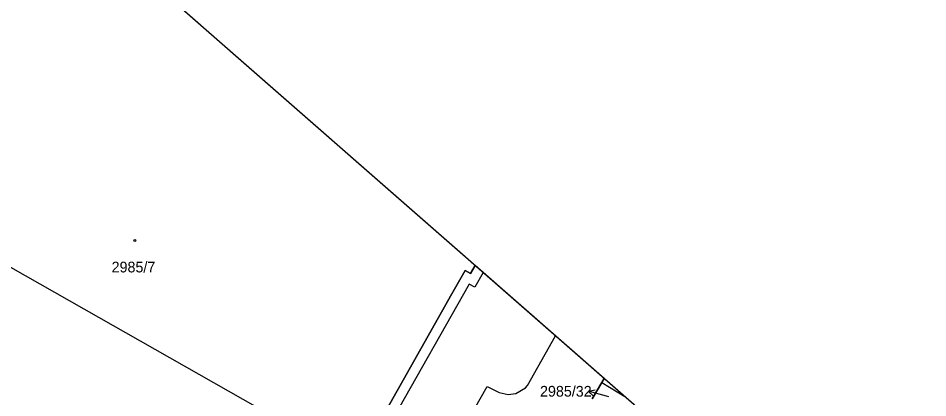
# Model space of a CAD drawing. Extents: x -620475 to -619963, y -1123010 to -1122510.
# Drawn here: x -620107.7 to -619962.9, y -1122744.6 to -1122684.3 of the extents above; entities that cross this region are included whole.
import ezdxf

# ---------------------------------------------------------------- set-up
doc = ezdxf.new("R2010")
doc.units = 0
for name, color, linetype in [('Hranice parcel', 7, 'Continuous'), ('Parcelní čísla', 7, 'Continuous'), ('Pop  PČ popisy', 7, 'Continuous'), ('Rámečky', 7, 'Continuous'), ('Rámečky-tisk', 7, 'Continuous'), ('Vnitřní kresba', 7, 'Continuous'), ('Věcná břemena k části', 7, 'Continuous'), ('Značky budov', 7, 'Continuous')]:
    doc.layers.add(name, color=color, linetype=linetype)

msp = doc.modelspace()

# ---------------------------------------------------------------- linework, layer by layer
at = {"layer": 'Hranice parcel'}
for p, q in [((-620014.43, -1122741.56), (-620014.82, -1122742.21)), ((-620014.82, -1122742.21), (-620016.36, -1122744.78)), ((-620014.82, -1122742.21), (-620011.18, -1122744.41))]:
    msp.add_line(p, q, dxfattribs=at)
for points in [[(-620129.52, -1122710.96), (-620124.48, -1122713.98), (-620124.94, -1122714.79), (-620058.31, -1122752.59), (-620054.51, -1122754.74), (-620054.56, -1122754.84)], [(-620054.56, -1122754.84), (-620053.98, -1122755.17), (-620038.67, -1122728.11), (-620036.56, -1122724.38), (-620035.71, -1122724.86), (-620034.98, -1122723.59)]]:
    msp.add_lwpolyline(points, dxfattribs=at)
at = {"layer": 'Pop  PČ popisy'}
for p, q in [((-620016.98, -1122743.6), (-620015.88, -1122743.38)), ((-620014.08, -1122744.38), (-620016.98, -1122743.6)), ((-620016.98, -1122743.6), (-620016.14, -1122744.35)), ((-620013.72, -1122744.48), (-620014.08, -1122744.38))]:
    msp.add_line(p, q, dxfattribs=at)
at = {"layer": 'Rámečky'}
msp.add_line((-619962.95, -1122786.6), (-620279.07, -1122510.07), dxfattribs=at)
at = {"layer": 'Rámečky-tisk'}
msp.add_lwpolyline([(-620158.49, -1123010.14), (-619962.95, -1122786.6), (-620279.07, -1122510.07)], dxfattribs=at)
at = {"layer": 'Vnitřní kresba'}
for p, q in [((-620033.71, -1122724.7), (-620035.03, -1122727.06)), ((-620035.9, -1122726.57), (-620054.1, -1122758.47)), ((-620035.03, -1122727.06), (-620035.9, -1122726.57)), ((-620026.67, -1122742.66), (-620022.17, -1122734.8)), ((-620041.55, -1122757.64), (-620033.04, -1122742.83)), ((-620033.04, -1122742.83), (-620031.15, -1122743.81)), ((-620028.49, -1122743.97), (-620026.97, -1122743.05)), ((-620026.97, -1122743.05), (-620026.67, -1122742.66)), ((-620031.15, -1122743.81), (-620029.7, -1122744.11)), ((-620029.7, -1122744.11), (-620028.49, -1122743.97))]:
    msp.add_line(p, q, dxfattribs=at)
at = {"layer": 'Věcná břemena k části'}
msp.add_line((-620014.43, -1122741.56), (-620034.98, -1122723.59), dxfattribs=at)
msp.add_line((-620014.43, -1122741.56), (-620034.98, -1122723.59), dxfattribs=at)
msp.add_line((-620014.43, -1122741.56), (-620034.98, -1122723.59), dxfattribs=at)
msp.add_line((-620014.43, -1122741.56), (-620034.98, -1122723.59), dxfattribs=at)
for points in [[(-620034.98, -1122723.59), (-620035.71, -1122724.86), (-620036.56, -1122724.38), (-620038.67, -1122728.11), (-620053.98, -1122755.17)], [(-620034.98, -1122723.59), (-620035.71, -1122724.86), (-620036.56, -1122724.38), (-620038.67, -1122728.11), (-620053.98, -1122755.17)], [(-620034.98, -1122723.59), (-620035.71, -1122724.86), (-620036.56, -1122724.38), (-620038.67, -1122728.11), (-620053.98, -1122755.17)], [(-620034.98, -1122723.59), (-620035.71, -1122724.86), (-620036.56, -1122724.38), (-620038.67, -1122728.11), (-620053.98, -1122755.17)], [(-620016.36, -1122744.78), (-620014.82, -1122742.21), (-620014.43, -1122741.56)], [(-620016.36, -1122744.78), (-620014.82, -1122742.21), (-620014.43, -1122741.56)], [(-620016.36, -1122744.78), (-620014.82, -1122742.21), (-620014.43, -1122741.56)], [(-620016.36, -1122744.78), (-620014.82, -1122742.21), (-620014.43, -1122741.56)]]:
    msp.add_lwpolyline(points, dxfattribs=at)
at = {"layer": 'Značky budov'}
msp.add_circle((-620089.13, -1122719.61), 0.175, dxfattribs=at)

# ---------------------------------------------------------------- texts
at = {"layer": 'Parcelní čísla'}
for s, p in [('2985/7', (-620092.82, -1122724.69)), ('2985/32', (-620024.65, -1122744.44))]:
    msp.add_text(s, height=1.7, dxfattribs=at).set_placement(p)

doc.saveas('drawing.dxf')
